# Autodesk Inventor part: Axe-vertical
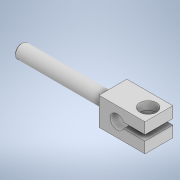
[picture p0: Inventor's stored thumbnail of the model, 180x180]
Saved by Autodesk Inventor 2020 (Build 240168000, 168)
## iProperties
Created: 2023-10
Part Number: Axe-vertical
Material: Générique
Document SubType Name: Modeling
Designer: bruno
Density: 1 g/cm^3
Appearance: Par défaut
Author: bruno
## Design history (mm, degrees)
sketch "Esquisse1"
  geometry: L1 (0, 0)-(10, 0); L2 (10, 0)-(10, -10); L3 (10, -10)-(0, -10); L4 (0, -10)-(0, 0)
  constraints: 8 end point, 2 parallel, 1 horizontal, 1 perpendicular
  dimensions: "d0" = 10 distance of L2.end L3.end; "d1" = 10 distance of L1.end L2.end
extrude "Extrusion1" new body sketch "Esquisse1" distance "d2" = 16.5; taper "d3" = 0 deg
sketch "Esquisse2"
  geometry: L1 (0, 10)-(0, 0) reference; L2 (0, 0)-(16.5, 0) reference; L3 (16.5, 10)-(16.5, 0) reference; L4 (0, 10)-(16.5, 10) reference; L5 (8.25, 6)-(17.658, 6); L6 (17.658, 6)-(17.658, 4); L7 (17.658, 4)-(8.25, 4); L8 (8.25, 4)-(8.25, 6); C1 r 2.5 at (6.5, 5); 3 further points
  constraints: 8 end point, 2 parallel, 1 centre point, 1 horizontal, 1 perpendicular
  dimensions: "d4" = 5 diameter of C1; "d5" = 10 distance from line of L3 C1.centre; "d6" = 2 distance of L5.end L6.end; "d7" = 1 distance from line of C1.centre L5
extrude "Extrusion2" cut sketch "Esquisse2" distance "d8" = 16.5; taper "d9" = 0 deg
sketch "Esquisse3"
  geometry: L1 (8.791, 0)-(8.791, 10) reference; L2 (16.5, 10)-(16.5, 0) reference; L3 (8.791, 0)-(16.5, 10); C1 r 3 at (12.646, 5); 1 further point
  constraints: 2 end point, 1 centre point, 1 midpoint
  dimensions: "d10" = 6 diameter of C1
extrude "Extrusion3" cut sketch "Esquisse3" distance "d11" = 3; taper "d12" = 0 deg
sketch "Esquisse4"
  geometry: C1 r 1.5 at (0, 0); 1 further point
  constraints: 1 centre point
  dimensions: "d13" = 3 diameter of C1
extrude "Extrusion4" cut sketch "Esquisse4" distance "d14" = 15; taper "d15" = 0 deg
feature "Filetage1" dims "d16" = 4, "d17" = 0
sketch "Esquisse5"
  geometry: L1 (0, 10)-(0, 0) reference; L2 (-10, 10)-(0, 10) reference; L3 (-10, 0)-(-10, 10) reference; L4 (0, 0)-(-10, 0) reference; L5 (-10, 10)-(0, 10) reference; L6 (-10, 0)-(-10, 4) reference; L7 (0, 10)-(-10, 0); C1 r 2.5 at (-5, 5); 1 further point
  constraints: 2 end point, 1 centre point, 1 midpoint
  dimensions: "d18" = 5 diameter of C1
extrude "Extrusion5" join sketch "Esquisse5" distance "d19" = 33; taper "d20" = 0 deg
chamfer "Chanfrein1" distance "d21" = 0.5; stored, may be unused: second distance "d22" = 2, angle "d23" = 45 deg
node "Solide1"
node "Boucle projetée1"
node "Boucle projetée2"
